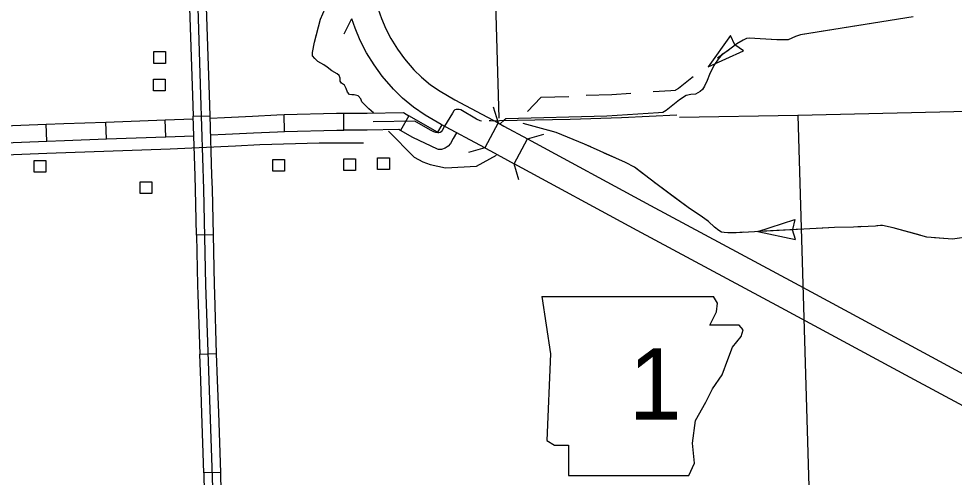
# Model space of a CAD drawing. Extents: x 155 to 3386, y 68 to 2138.
# Drawn here: x 1365.4 to 1602.6, y 794.9 to 911.3 of the extents above; entities that cross this region are included whole.
import ezdxf

# ---------------------------------------------------------------- set-up
doc = ezdxf.new("R2010")
doc.units = 0
for name, color, linetype in [('Level 10', 7, 'Continuous'), ('Level 21', 7, 'Continuous'), ('Level 31', 7, 'Continuous'), ('Level 32', 7, 'Continuous'), ('Level 34', 7, 'Continuous'), ('Level 35', 7, 'Continuous'), ('Level 37', 7, 'Continuous'), ('Level 43', 7, 'Continuous'), ('Level 5', 7, 'Continuous'), ('Level 56', 7, 'Continuous'), ('Level 6', 7, 'Continuous')]:
    doc.layers.add(name, color=color, linetype=linetype)

msp = doc.modelspace()

# ---------------------------------------------------------------- linework, layer by layer
at = {"layer": 'Level 10'}
for p, q in [((1486.91, 884.81), (1483.53, 878.52)), ((1491.01, 874.47), (1494.41, 880.75))]:
    msp.add_line(p, q, dxfattribs=at)
for points in [[(1456.56, 913.66), (1457.39, 911.35), (1458.43, 908.69), (1459.74, 906.21), (1461.44, 903.5), (1463.17, 901.07), (1465.56, 898.29), (1467.5, 896.43), (1469.83, 894.48), (1472.23, 892.84), (1475.97, 890.67), (1486.91, 884.81)], [(1483.53, 878.52), (1472.49, 884.43), (1468.42, 886.8), (1465.52, 888.78), (1462.73, 891.11), (1460.37, 893.38), (1457.55, 896.65), (1455.5, 899.52), (1453.55, 902.63), (1451.92, 905.7), (1450.7, 908.85), (1449.83, 911.26)], [(1486.91, 884.81), (1488.41, 884.01), (1494.41, 880.75)], [(1494.41, 880.75), (1525.58, 863.85), (1562.1, 844.22), (1594.76, 826.56), (1615.06, 815.59)], [(1483.53, 878.52), (1485.02, 877.72), (1491.01, 874.47)], [(1611.67, 809.31), (1591.37, 820.27), (1558.71, 837.93), (1522.19, 857.57), (1491.01, 874.47)]]:
    msp.add_lwpolyline(points, dxfattribs=at)
at = {"layer": 'Level 21'}
for p, q in [((1498.05, 840.78), (1500.22, 826.28)), ((1542.52, 839.09), (1541.51, 840.76)), ((1542.27, 836.92), (1542.52, 839.09)), ((1540.58, 833.53), (1542.27, 836.92)), ((1548.07, 833.53), (1540.58, 833.53)), ((1549.04, 832.32), (1548.07, 833.53)), ((1546.38, 827.97), (1548.56, 830.63)), ((1548.56, 830.63), (1549.04, 832.32)), ((1545.17, 824.83), (1546.38, 827.97)), ((1500.22, 826.28), (1499.25, 804.29)), ((1543.72, 820.96), (1545.17, 824.83)), ((1541.31, 817.34), (1543.72, 820.96)), ((1539.62, 813.95), (1541.31, 817.34)), ((1536.96, 809.36), (1539.62, 813.95)), ((1536.23, 803.56), (1536.96, 809.36)), ((1499.25, 804.29), (1501.19, 803.08)), ((1501.19, 803.08), (1504.81, 803.08)), ((1504.81, 803.08), (1504.81, 795.35)), ((1536.71, 798.49), (1536.23, 803.56)), ((1535.26, 795.35), (1536.71, 798.49)), ((1504.81, 795.35), (1535.26, 795.35))]:
    msp.add_line(p, q, dxfattribs=at)
msp.add_lwpolyline([(1498.05, 840.78), (1541.51, 840.76)], dxfattribs=at)
at = {"layer": 'Level 31'}
for p, q in [((1447.83, 883), (1447.83, 887.28)), ((1409.61, 886.5), (1413.89, 886.64)), ((1464.31, 886.63), (1462.19, 882.91)), ((1414.73, 856.46), (1410.45, 856.37)), ((1414.73, 856.46), (1414.73, 856.46)), ((1411.29, 826.18), (1415.57, 826.33)), ((1416.61, 796.18), (1412.32, 796.03)), ((1416.61, 796.18), (1416.61, 796.18))]:
    msp.add_line(p, q, dxfattribs=at)
for points in [[(1420.96, 585), (1420.5, 602.36), (1419.65, 626.77), (1419.02, 651.18), (1418.35, 675.21), (1417.43, 699.69), (1416.62, 724.28), (1415.88, 748.76), (1415.17, 772.25), (1414.5, 794.97), (1413.66, 819.52), (1412.85, 843.76), (1412.35, 867.99), (1411.58, 891.84), (1410.77, 916.92), (1409.92, 941.23), (1409.21, 964.58), (1408.72, 989.66), (1407.91, 1014.21), (1407.76, 1018.97)], [(1408.63, 916.66), (1409.12, 901.58)], [(1413.4, 901.72), (1412.91, 916.8)], [(1409.12, 901.58), (1409.44, 891.77), (1409.61, 886.5)], [(1413.89, 886.64), (1413.72, 891.91), (1413.4, 901.72)], [(1447.83, 887.28), (1453.7, 887.28), (1462.91, 887.44), (1464.31, 886.63)], [(1482.71, 885.31), (1482.41, 885.35), (1481.43, 885.77), (1477.46, 888.11), (1477.04, 888.2), (1476.73, 888.22), (1476.33, 888.2), (1476, 888.11), (1475.72, 887.85), (1475.34, 887.32), (1473.33, 883.98), (1472.76, 882.88), (1472.49, 882.59), (1472.21, 882.39), (1471.92, 882.3), (1471.61, 882.3), (1471.12, 882.37), (1470.66, 882.55), (1469.82, 882.99), (1465.8, 885.28), (1455.26, 885.11)], [(1410.1, 871.43), (1409.61, 886.5)], [(1414.38, 871.57), (1413.89, 886.64)], [(1471.53, 882.51), (1464.31, 886.63)], [(1462.19, 882.91), (1461.8, 883.13), (1453.77, 883), (1447.83, 883)], [(1471.59, 878.16), (1465.34, 881.11), (1462.19, 882.91)], [(1472.64, 884.35), (1471.53, 882.51)], [(1476.42, 882.32), (1475.56, 880.9), (1474.89, 879.6), (1474.27, 878.93), (1473.52, 878.4), (1472.6, 878.12), (1471.83, 878.12), (1471.59, 878.16)], [(1410.45, 856.37), (1410.21, 867.94), (1410.1, 871.43)], [(1414.73, 856.46), (1414.49, 868.05), (1414.38, 871.57)], [(1410.45, 856.37), (1410.7, 843.7), (1410.79, 841.26)], [(1415.07, 841.4), (1414.99, 843.82), (1414.73, 856.46)], [(1410.79, 841.26), (1411.29, 826.18)], [(1415.57, 826.33), (1415.07, 841.4)], [(1411.8, 811.1), (1411.52, 819.45), (1411.29, 826.18)], [(1416.09, 811.25), (1415.8, 819.6), (1415.57, 826.33)], [(1412.32, 796.03), (1411.8, 811.1)], [(1416.61, 796.18), (1416.09, 811.25)], [(1412.32, 796.03), (1412.36, 794.9), (1412.77, 780.96)], [(1417.06, 781.09), (1416.65, 795.04), (1416.61, 796.18)]]:
    msp.add_lwpolyline(points, dxfattribs=at)
at = {"layer": 'Level 32'}
for p, q in [((1387.6, 880.76), (1387.45, 885.05)), ((1402.68, 881.29), (1402.53, 885.58)), ((1432.8, 882.64), (1432.69, 886.92)), ((1372.54, 880.21), (1372.37, 884.5))]:
    msp.add_line(p, q, dxfattribs=at)
for points in [[(1432.69, 886.92), (1445.95, 887.28), (1447.83, 887.28)], [(1372.37, 884.5), (1376.84, 884.68), (1387.45, 885.05)], [(1387.45, 885.05), (1402.53, 885.58)], [(1402.53, 885.58), (1409.63, 885.83)], [(1413.91, 886.05), (1417.58, 886.22)], [(1417.58, 886.22), (1424.67, 886.55), (1430.86, 886.87), (1432.69, 886.92)], [(1487.26, 885.34), (1485.64, 885.31), (1485.12, 885.32), (1484.68, 885.34)], [(1357.29, 883.89), (1372.37, 884.5)], [(1417.78, 881.94), (1424.88, 882.27), (1431.03, 882.59), (1432.8, 882.64)], [(1432.8, 882.64), (1446.01, 883), (1447.83, 883)], [(1357.47, 879.61), (1372.54, 880.21)], [(1372.54, 880.21), (1377, 880.39), (1387.6, 880.76)], [(1387.6, 880.76), (1402.68, 881.29)], [(1402.68, 881.29), (1409.77, 881.54)], [(1414.05, 881.76), (1417.78, 881.94)], [(1323.72, 875.17), (1372.53, 877.14), (1403.79, 878.24), (1420.38, 879.01), (1426.55, 879.33), (1441.59, 879.75), (1452.83, 879.75)]]:
    msp.add_lwpolyline(points, dxfattribs=at)
at = {"layer": 'Level 34'}
msp.add_lwpolyline([(1532.22, 886.83), (1518.19, 886.15), (1505.23, 885.67), (1487.26, 885.34)], dxfattribs=at)
at = {"layer": 'Level 35'}
for points in [[(1455.31, 887.39), (1454.17, 888.36), (1453.1, 889.43), (1452.39, 890.14), (1452.09, 890.95), (1451.43, 891.71), (1450.41, 891.92), (1449.85, 891.92), (1449.24, 892.02), (1448.73, 892.63), (1448.43, 893.54), (1447.97, 894.36), (1447.21, 894.92), (1446.9, 895.43), (1446.9, 896.14), (1446.65, 896.85), (1446.09, 897.31), (1444.77, 898.02), (1443.6, 898.93), (1442.74, 899.54), (1441.21, 900.41), (1440.45, 901.17), (1439.89, 901.83), (1439.89, 902.34), (1439.89, 902.7)], [(1459.16, 882.73), (1465.66, 876.12), (1467.83, 874.93), (1469.67, 874.28), (1473.56, 873.41), (1481.47, 873.85), (1486.56, 876.67)]]:
    msp.add_lwpolyline(points, dxfattribs=at)
at = {"layer": 'Level 37'}
for points in [[(1447.93, 907.46), (1449.82, 911.31)], [(1485.66, 888.92), (1486.91, 884.81)], [(1494.41, 880.75), (1498.52, 881.97)], [(1483.53, 878.52), (1479.43, 877.28)], [(1492.23, 870.36), (1491.01, 874.47)]]:
    msp.add_lwpolyline(points, dxfattribs=at)
at = {"layer": 'Level 43'}
for p, q in [((1545.88, 907.01), (1540.21, 899.01)), ((1546.97, 904.64), (1545.88, 907.01)), ((1549.12, 903.1), (1546.99, 904.61)), ((1540.21, 899.01), (1549.12, 903.1))]:
    msp.add_line(p, q, dxfattribs=at)
for points in [[(1439.89, 902.7), (1440.35, 905.27), (1441.87, 911.16), (1443.09, 913.86), (1443.6, 915.49), (1444.21, 916.91), (1444.36, 917.83), (1444.26, 918.94), (1443.85, 920.32), (1442.58, 925.55), (1441.92, 928.1), (1441.11, 930.84)], [(1592.16, 911.77), (1563.59, 907.2), (1562.32, 906.74), (1560.44, 905.93), (1559.99, 905.88), (1557.6, 905.88), (1550.58, 906.33), (1549.92, 906.23), (1549.11, 905.82), (1547.43, 904.86), (1544.94, 902.98), (1543.77, 902.27), (1542.71, 900.99), (1541.64, 899.42), (1540.57, 897.08), (1539.91, 895.6), (1539.3, 894.18), (1538.79, 893.27), (1538.18, 892.76), (1537.01, 892.15), (1535.79, 892.04), (1534.63, 891.74), (1532.9, 890.67), (1529.54, 887.98), (1528.68, 887.47), (1527.61, 887.37), (1514.5, 886.5), (1488.92, 885.84), (1488.48, 885.52), (1487.51, 884.65)], [(1585.86, 910.76), (1574.68, 908.97)], [(1439.89, 902.7), (1440.35, 905.27), (1441.11, 908.22)], [(1556.22, 905.97), (1550.58, 906.33), (1549.92, 906.23), (1549.11, 905.82), (1547.43, 904.86), (1545.72, 903.56), (1542.55, 901.21)], [(1570.96, 908.38), (1563.59, 907.2), (1562.32, 906.74), (1560.44, 905.93), (1559.99, 905.88)], [(1536.4, 896.49), (1536.06, 896.28), (1532.7, 893.58), (1531.88, 893.1)], [(1520.56, 892.28), (1515.74, 891.96), (1509.26, 891.79)], [(1531.88, 893.1), (1531.84, 893.07), (1530.77, 892.97), (1526.25, 892.67)], [(1504.84, 891.48), (1497.73, 891.29), (1494.35, 887.72)], [(1606.81, 856), (1602.18, 855.37), (1595.64, 855.85), (1587.06, 858.2), (1584.37, 858.82), (1583.86, 858.82), (1582.59, 858.66), (1577.05, 858.41), (1572.22, 858.26), (1547.27, 856.98), (1545.17, 856.92), (1544.23, 857), (1543.57, 857.15), (1542.89, 857.51), (1541.77, 858.34), (1540.27, 859.82), (1538.77, 860.94), (1535.14, 863.38), (1526.95, 869.43), (1521.5, 873.56), (1519.27, 874.78), (1516.78, 875.85), (1508.8, 879.46), (1501.68, 882.41), (1493.32, 884.65)], [(1510.42, 878.73), (1508.8, 879.46), (1501.68, 882.41), (1499.91, 882.88)], [(1523.77, 871.84), (1521.5, 873.56), (1519.27, 874.78), (1516.78, 875.85), (1513.85, 877.17)], [(1531.33, 866.2), (1526.95, 869.43), (1526.78, 869.56)], [(1535.9, 862.87), (1535.14, 863.38), (1531.33, 866.2)], [(1549.03, 857.07), (1547.27, 856.98), (1545.17, 856.92), (1544.23, 857), (1543.57, 857.15), (1542.89, 857.51), (1541.77, 858.34), (1540.27, 859.82), (1539.02, 860.75)], [(1552.8, 857.27), (1562.18, 860.29), (1561.58, 857.75)], [(1593.92, 856.33), (1587.06, 858.2), (1584.37, 858.82), (1583.86, 858.82), (1582.93, 858.7)], [(1564.1, 857.84), (1552.8, 857.27)], [(1552.8, 857.27), (1562.33, 855.21), (1561.58, 857.71)], [(1579.17, 858.51), (1577.05, 858.41), (1572.22, 858.26), (1567.86, 858.03)], [(1608.88, 856.03), (1606.81, 856), (1602.18, 855.37), (1597.62, 855.71)]]:
    msp.add_lwpolyline(points, dxfattribs=at)
at = {"layer": 'Level 5'}
msp.add_lwpolyline([(1562.97, 886.74), (1567.34, 738.35)], dxfattribs=at)
at = {"layer": 'Level 56'}
for points in [[(1399.62, 899.93), (1399.62, 902.9), (1402.61, 902.9), (1402.61, 899.93)], [(1399.53, 892.93), (1399.53, 895.9), (1402.51, 895.9), (1402.51, 892.93)], [(1369.26, 872.36), (1369.26, 875.33), (1372.24, 875.33), (1372.24, 872.36)], [(1429.81, 872.61), (1429.81, 875.58), (1432.8, 875.58), (1432.8, 872.61)], [(1447.83, 872.75), (1447.83, 875.73), (1450.81, 875.73), (1450.81, 872.75)], [(1456.39, 873), (1456.39, 875.98), (1459.37, 875.98), (1459.37, 873)], [(1396.18, 866.93), (1396.18, 869.9), (1399.16, 869.9), (1399.16, 866.93)]]:
    msp.add_lwpolyline(points, close=True, dxfattribs=at)
at = {"layer": 'Level 6'}
for points in [[(1487.24, 886.06), (1483.35, 1020.26), (1411.81, 1019.04)], [(1638.52, 888.52), (1562.97, 886.74), (1532.94, 886.19)]]:
    msp.add_lwpolyline(points, dxfattribs=at)

# ---------------------------------------------------------------- texts
at = {"layer": 'Level 21'}
msp.add_text('1', height=18.1, dxfattribs=at).set_placement((1520.04, 809.58))

doc.saveas('drawing.dxf')
